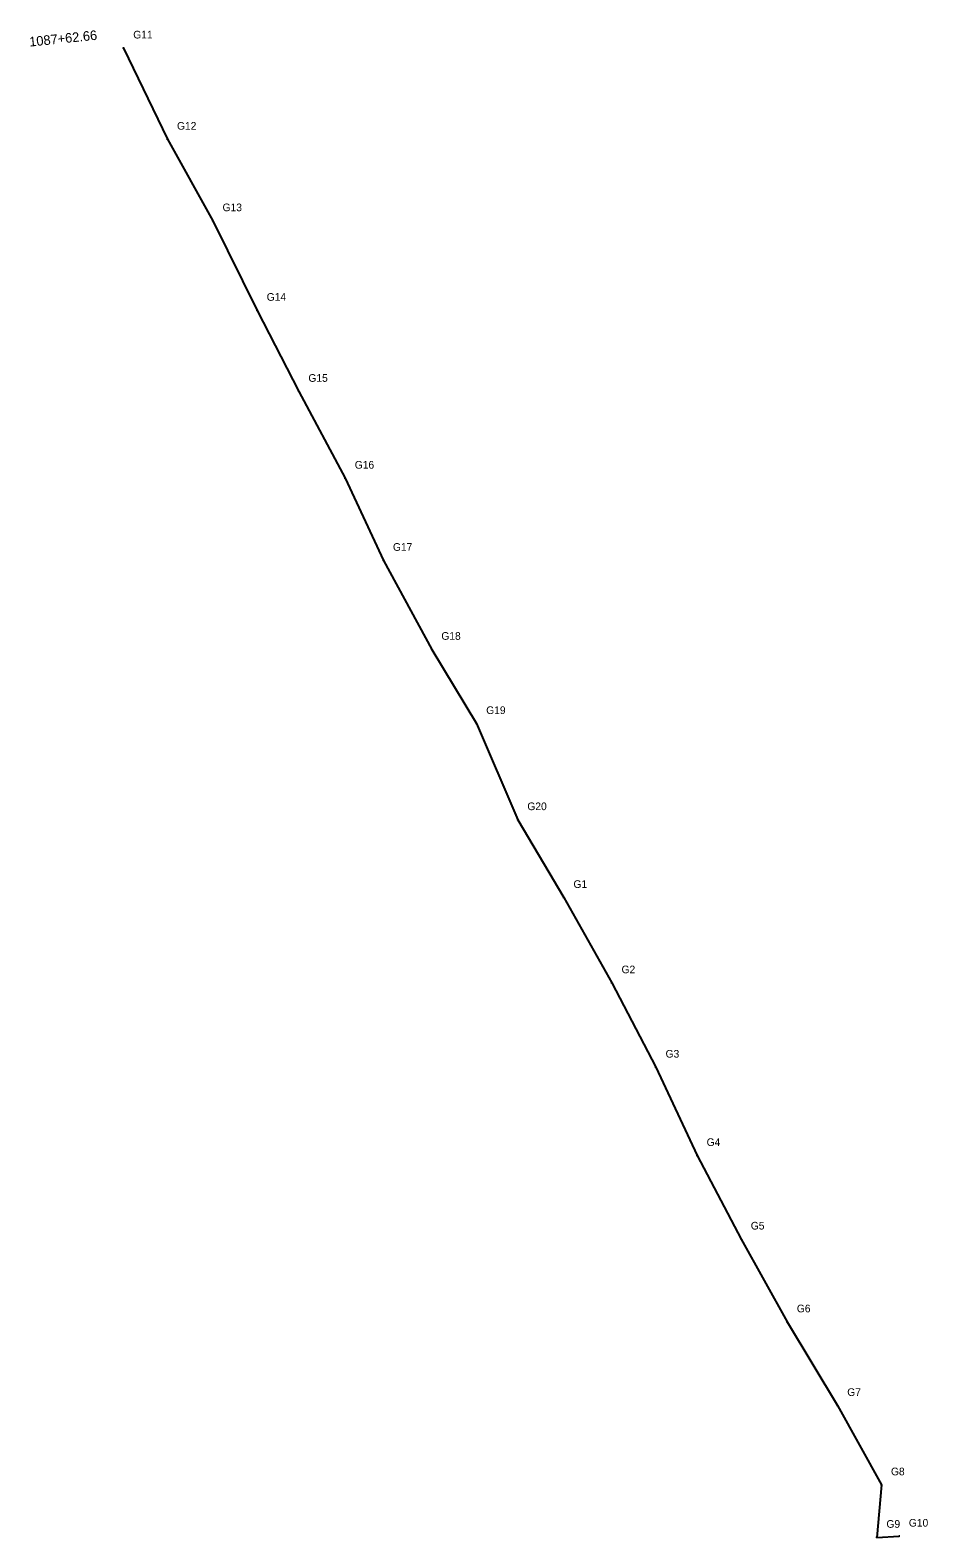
# Model space of a CAD drawing. Extents: x 1726967 to 1727435, y 654929 to 655714.
import ezdxf

# ---------------------------------------------------------------- set-up
doc = ezdxf.new("R2010")
doc.units = 0
for name, color, linetype in [('Level 21', 7, 'Continuous'), ('Level 32', 7, 'Continuous'), ('SURVEY - DRAINAGE - Storm Sewer - Points - Locators', 7, 'Continuous'), ('SURVEY - DRAINAGE - Storm Sewer - Points - Numbers', 7, 'Continuous')]:
    doc.layers.add(name, color=color, linetype=linetype)

msp = doc.modelspace()

# ---------------------------------------------------------------- linework, layer by layer
at = {"layer": 'Level 21'}
for p, q in [((1727015.97, 655705.12), (1727038.76, 655657.57)), ((1727038.76, 655657.57), (1727062.52, 655615.08)), ((1727062.52, 655615.08), (1727085.53, 655568.4)), ((1727085.53, 655568.4), (1727107.26, 655526.17)), ((1727107.26, 655526.17), (1727131.43, 655480.91)), ((1727131.43, 655480.91), (1727151.33, 655438.1)), ((1727151.33, 655438.1), (1727176.56, 655391.72)), ((1727176.56, 655391.72), (1727199.95, 655353.02)), ((1727199.95, 655353.02), (1727221.39, 655302.93)), ((1727221.39, 655302.93), (1727245.42, 655262.39)), ((1727245.42, 655262.39), (1727270.49, 655217.91)), ((1727270.49, 655217.91), (1727293.44, 655173.96)), ((1727293.44, 655173.96), (1727314.83, 655127.89)), ((1727314.83, 655127.89), (1727337.85, 655084.35)), ((1727337.85, 655084.35), (1727361.86, 655041.2)), ((1727361.86, 655041.2), (1727388.13, 654997.62)), ((1727388.13, 654997.62), (1727410.91, 654956.25)), ((1727410.91, 654956.25), (1727408.57, 654928.92)), ((1727408.57, 654928.92), (1727420.24, 654929.51))]:
    msp.add_line(p, q, dxfattribs=at)
at = {"layer": 'SURVEY - DRAINAGE - Storm Sewer - Points - Locators'}
for p, q in [((1727016.22, 655705.12), (1727015.72, 655705.12)), ((1727015.97, 655704.87), (1727015.97, 655705.37)), ((1727015.97, 655705.12), (1727015.97, 655705.12)), ((1727015.97, 655705.12), (1727015.97, 655705.12)), ((1727039.01, 655657.57), (1727038.51, 655657.57)), ((1727038.76, 655657.32), (1727038.76, 655657.82)), ((1727038.76, 655657.57), (1727038.76, 655657.57)), ((1727038.76, 655657.57), (1727038.76, 655657.57)), ((1727062.77, 655615.08), (1727062.27, 655615.08)), ((1727062.52, 655614.83), (1727062.52, 655615.33)), ((1727062.52, 655615.08), (1727062.52, 655615.08)), ((1727062.52, 655615.08), (1727062.52, 655615.08)), ((1727085.78, 655568.4), (1727085.28, 655568.4)), ((1727085.53, 655568.15), (1727085.53, 655568.65)), ((1727085.53, 655568.4), (1727085.53, 655568.4)), ((1727085.53, 655568.4), (1727085.53, 655568.4)), ((1727107.51, 655526.17), (1727107.01, 655526.17)), ((1727107.26, 655525.92), (1727107.26, 655526.42)), ((1727107.26, 655526.17), (1727107.26, 655526.17)), ((1727107.26, 655526.17), (1727107.26, 655526.17)), ((1727131.68, 655480.91), (1727131.18, 655480.91)), ((1727131.43, 655480.66), (1727131.43, 655481.16)), ((1727131.43, 655480.91), (1727131.43, 655480.91)), ((1727131.43, 655480.91), (1727131.43, 655480.91)), ((1727151.58, 655438.1), (1727151.08, 655438.1)), ((1727151.33, 655437.85), (1727151.33, 655438.35)), ((1727151.33, 655438.1), (1727151.33, 655438.1)), ((1727151.33, 655438.1), (1727151.33, 655438.1)), ((1727176.81, 655391.72), (1727176.31, 655391.72)), ((1727176.56, 655391.47), (1727176.56, 655391.97)), ((1727176.56, 655391.72), (1727176.56, 655391.72)), ((1727176.56, 655391.72), (1727176.56, 655391.72)), ((1727200.2, 655353.02), (1727199.7, 655353.02)), ((1727199.95, 655352.77), (1727199.95, 655353.27)), ((1727199.95, 655353.02), (1727199.95, 655353.02)), ((1727199.95, 655353.02), (1727199.95, 655353.02)), ((1727221.64, 655302.93), (1727221.14, 655302.93)), ((1727221.39, 655302.68), (1727221.39, 655303.18)), ((1727221.39, 655302.93), (1727221.39, 655302.93)), ((1727221.39, 655302.93), (1727221.39, 655302.93)), ((1727245.67, 655262.39), (1727245.17, 655262.39)), ((1727245.42, 655262.14), (1727245.42, 655262.64)), ((1727245.42, 655262.39), (1727245.42, 655262.39)), ((1727245.42, 655262.39), (1727245.42, 655262.39)), ((1727270.74, 655217.91), (1727270.24, 655217.91)), ((1727270.49, 655217.66), (1727270.49, 655218.16)), ((1727270.49, 655217.91), (1727270.49, 655217.91)), ((1727270.49, 655217.91), (1727270.49, 655217.91)), ((1727293.69, 655173.96), (1727293.19, 655173.96)), ((1727293.44, 655173.71), (1727293.44, 655174.21)), ((1727293.44, 655173.96), (1727293.44, 655173.96)), ((1727293.44, 655173.96), (1727293.44, 655173.96)), ((1727315.08, 655127.89), (1727314.58, 655127.89)), ((1727314.83, 655127.64), (1727314.83, 655128.14)), ((1727314.83, 655127.89), (1727314.83, 655127.89)), ((1727314.83, 655127.89), (1727314.83, 655127.89)), ((1727338.1, 655084.35), (1727337.6, 655084.35)), ((1727337.85, 655084.1), (1727337.85, 655084.6)), ((1727337.85, 655084.35), (1727337.85, 655084.35)), ((1727337.85, 655084.35), (1727337.85, 655084.35)), ((1727361.86, 655040.95), (1727361.86, 655041.45)), ((1727362.11, 655041.2), (1727361.61, 655041.2)), ((1727361.86, 655041.2), (1727361.86, 655041.2)), ((1727361.86, 655041.2), (1727361.86, 655041.2)), ((1727388.38, 654997.62), (1727387.88, 654997.62)), ((1727388.13, 654997.37), (1727388.13, 654997.87)), ((1727388.13, 654997.62), (1727388.13, 654997.62)), ((1727388.13, 654997.62), (1727388.13, 654997.62)), ((1727411.16, 654956.25), (1727410.66, 654956.25)), ((1727410.91, 654956), (1727410.91, 654956.5)), ((1727410.91, 654956.25), (1727410.91, 654956.25)), ((1727410.91, 654956.25), (1727410.91, 654956.25)), ((1727408.82, 654928.92), (1727408.32, 654928.92)), ((1727408.57, 654928.67), (1727408.57, 654929.17)), ((1727408.57, 654928.92), (1727408.57, 654928.92)), ((1727408.57, 654928.92), (1727408.57, 654928.92)), ((1727420.49, 654929.51), (1727419.99, 654929.51)), ((1727420.24, 654929.26), (1727420.24, 654929.76)), ((1727420.24, 654929.51), (1727420.24, 654929.51)), ((1727420.24, 654929.51), (1727420.24, 654929.51))]:
    msp.add_line(p, q, dxfattribs=at)

# ---------------------------------------------------------------- texts
at = {"layer": 'Level 32'}
msp.add_text('1087+62.66', height=5, rotation=5.85591, dxfattribs=at).set_placement((1726967.02, 655705.85))
at = {"layer": 'SURVEY - DRAINAGE - Storm Sewer - Points - Numbers'}
for s, p in [('G11', (1727020.97, 655710.12)), ('G12', (1727043.76, 655662.57)), ('G13', (1727067.52, 655620.08)), ('G14', (1727090.53, 655573.4)), ('G15', (1727112.26, 655531.17)), ('G16', (1727136.43, 655485.91)), ('G17', (1727156.33, 655443.1)), ('G18', (1727181.56, 655396.72)), ('G19', (1727204.95, 655358.02)), ('G20', (1727226.39, 655307.93)), ('G1', (1727250.42, 655267.39)), ('G2', (1727275.49, 655222.91)), ('G3', (1727298.44, 655178.96)), ('G4', (1727319.83, 655132.89)), ('G5', (1727342.85, 655089.35)), ('G6', (1727366.86, 655046.2)), ('G7', (1727393.13, 655002.62)), ('G8', (1727415.91, 654961.25)), ('G9', (1727413.57, 654933.92)), ('G10', (1727425.24, 654934.51))]:
    msp.add_text(s, height=4, dxfattribs=at).set_placement(p)

doc.saveas('drawing.dxf')
